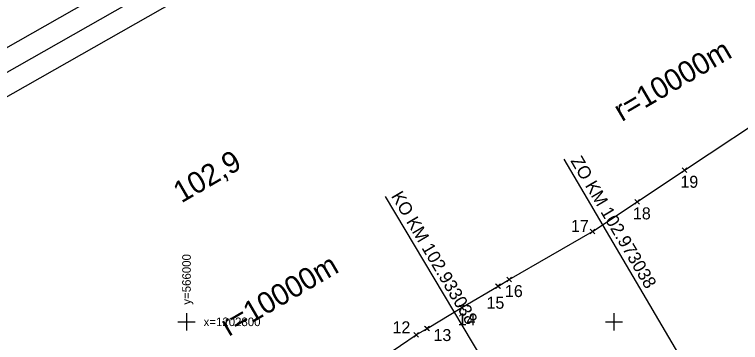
# Model space of a CAD drawing. Extents: x -566182 to -565305, y -1203073 to -1202401.
# Drawn here: x -566040.2 to -565870.4, y -1202804.8 to -1202728.2 of the extents above; entities that cross this region are included whole.
import ezdxf

# ---------------------------------------------------------------- set-up
doc = ezdxf.new("R2010")
doc.units = 0
for name, color, linetype in [('LÁTAL_SVRŠEK', 7, 'Continuous'), ('SZDC', 7, 'Continuous'), ('Vrstva 1', 7, 'Continuous'), ('Vrstva 39', 7, 'Continuous'), ('Vrstva 5', 7, 'Continuous'), ('Vrstva 6', 7, 'Continuous'), ('Vrstva 60', 7, 'Continuous'), ('Vrstva 7', 7, 'Continuous')]:
    doc.layers.add(name, color=color, linetype=linetype)

msp = doc.modelspace()

# ---------------------------------------------------------------- linework, layer by layer
at = {"layer": 'LÁTAL_SVRŠEK'}
msp.add_arc((-560804.84, -1211436.41), 10000, 120.189547, 120.512837, dxfattribs=at)
at = {"layer": 'SZDC'}
msp.add_lwpolyline([(-566109.86, -1202908.94), (-566097.96, -1202902.03), (-566084.51, -1202894.21), (-566065.16, -1202881.19), (-566062.89, -1202879.66), (-566050.93, -1202871.86), (-566034.12, -1202860.89), (-566014.69, -1202848.22), (-565999.33, -1202838.2), (-565981.56, -1202826.61), (-565964.56, -1202815.52), (-565946.25, -1202803.07), (-565943.74, -1202801.57), (-565935.57, -1202796.69), (-565927.13, -1202791.65), (-565924.54, -1202790.1), (-565905.03, -1202778.89), (-565894.6, -1202771.96), (-565883.49, -1202764.57), (-565860.68, -1202749.5), (-565834.73, -1202732.72)], dxfattribs=at)
at = {"layer": 'Vrstva 1'}
for points in [[(-566035.16, -1203073.47), (-565304.55, -1202658.99), (-565451.1, -1202400.68), (-566181.71, -1202815.16)], [(-565311.37, -1202657.11), (-566033.28, -1203066.66), (-566174.89, -1202817.04), (-565452.98, -1202407.49)], [(-566031.4, -1203059.85), (-565496.48, -1202756.39), (-565633.16, -1202515.46), (-566168.08, -1202818.92)]]:
    msp.add_lwpolyline(points, close=True, dxfattribs=at)
at = {"layer": 'Vrstva 5'}
for p, q in [((-566000, -1202798), (-566000, -1202802)), ((-565900, -1202798), (-565900, -1202802)), ((-566002, -1202800), (-565998, -1202800)), ((-565902, -1202800), (-565898, -1202800))]:
    msp.add_line(p, q, dxfattribs=at)
at = {"layer": 'Vrstva 6'}
msp.add_arc((-561050.64, -1211005.49), 9503.95, 120.13635, 120.525886, dxfattribs=at)
at = {"layer": 'Vrstva 60'}
for p, q in [((-565879.13, -1202817.16), (-565911.63, -1202762.03)), ((-565883.04, -1202765.02), (-565884.04, -1202764.02)), ((-565883.04, -1202764.12), (-565884.04, -1202765.12)), ((-565883.94, -1202765.02), (-565882.94, -1202764.02)), ((-565883.94, -1202764.12), (-565882.94, -1202765.12)), ((-565883.49, -1202764.57), (-565883.49, -1202764.57)), ((-565913.59, -1202837.48), (-565953.43, -1202770.71)), ((-565894.15, -1202772.41), (-565895.15, -1202771.41)), ((-565894.15, -1202771.51), (-565895.15, -1202772.51)), ((-565895.05, -1202772.41), (-565894.05, -1202771.41)), ((-565895.05, -1202771.51), (-565894.05, -1202772.51)), ((-565894.6, -1202771.96), (-565894.6, -1202771.96)), ((-565904.58, -1202779.34), (-565905.58, -1202778.34)), ((-565904.58, -1202778.44), (-565905.58, -1202779.44)), ((-565905.48, -1202779.34), (-565904.48, -1202778.34)), ((-565905.48, -1202778.44), (-565904.48, -1202779.44)), ((-565905.03, -1202778.89), (-565905.03, -1202778.89)), ((-565924.09, -1202790.55), (-565925.09, -1202789.55)), ((-565924.09, -1202789.65), (-565925.09, -1202790.65)), ((-565924.99, -1202790.55), (-565923.99, -1202789.55)), ((-565924.99, -1202789.65), (-565923.99, -1202790.65)), ((-565926.68, -1202792.1), (-565927.68, -1202791.1)), ((-565926.68, -1202791.2), (-565927.68, -1202792.2)), ((-565927.58, -1202792.1), (-565926.58, -1202791.1)), ((-565927.58, -1202791.2), (-565926.58, -1202792.2)), ((-565924.54, -1202790.1), (-565924.54, -1202790.1)), ((-565927.13, -1202791.65), (-565927.13, -1202791.65)), ((-565935.12, -1202797.14), (-565936.12, -1202796.14)), ((-565935.12, -1202796.24), (-565936.12, -1202797.24)), ((-565936.02, -1202797.14), (-565935.02, -1202796.14)), ((-565936.02, -1202796.24), (-565935.02, -1202797.24)), ((-565935.57, -1202796.69), (-565935.57, -1202796.69)), ((-565943.29, -1202802.02), (-565944.29, -1202801.02)), ((-565943.29, -1202801.12), (-565944.29, -1202802.12)), ((-565944.19, -1202802.02), (-565943.19, -1202801.02)), ((-565944.19, -1202801.12), (-565943.19, -1202802.12)), ((-565943.74, -1202801.57), (-565943.74, -1202801.57)), ((-565945.8, -1202803.52), (-565946.8, -1202802.52)), ((-565945.8, -1202802.62), (-565946.8, -1202803.62)), ((-565946.7, -1202803.52), (-565945.7, -1202802.52)), ((-565946.7, -1202802.62), (-565945.7, -1202803.62)), ((-565946.25, -1202803.07), (-565946.25, -1202803.07))]:
    msp.add_line(p, q, dxfattribs=at)

# ---------------------------------------------------------------- texts
at = {"layer": 'Vrstva 39'}
for s, height, rotation, p in [('r=10000m', 5, 30.331, (-565898.18, -1202753.35)), ('ZO KM 102.973038', 3, 300.517, (-565910.26, -1202762.38)), ('KO KM 102.933038', 3, 300.517, (-565952.22, -1202770.61)), ('r=10000m', 5, 30.335, (-565990.14, -1202803.53))]:
    msp.add_text(s, height=height, rotation=rotation, dxfattribs=at).set_placement(p)
at = {"layer": 'Vrstva 5'}
msp.add_text('y=566000', height=2, rotation=90, dxfattribs=at).set_placement((-565999, -1202796))
msp.add_text('x=1202800', height=2, dxfattribs=at).set_placement((-565996, -1202801))
at = {"layer": 'Vrstva 60'}
for s, p in [('19', (-565884.46, -1202768.68)), ('18', (-565895.57, -1202776.07)), ('17', (-565910.05, -1202778.99)), ('16', (-565925.51, -1202794.21)), ('15', (-565929.82, -1202796.95)), ('14', (-565936.54, -1202800.8)), ('12', (-565951.81, -1202802.68)), ('13', (-565942.22, -1202804.49))]:
    msp.add_text(s, height=2.8, dxfattribs=at).set_placement(p)
at = {"layer": 'Vrstva 7'}
msp.add_text('102,9', height=5, rotation=30.1698, dxfattribs=at).set_placement((-566001.2, -1202772.36))

doc.saveas('drawing.dxf')
